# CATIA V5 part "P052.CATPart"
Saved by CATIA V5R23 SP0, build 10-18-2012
Part number: P052
Definition: ISO 4762 Vis Chc M8x45
Publications: "Mating Edge", "Axis"
Bounding box of the stored display mesh (mm): x -45 to 8, y -6.5 to 6.5, z -6.453 to 6.453
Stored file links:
  C:\wamp\www\COURS\CONCEPTION GMP1\TITRE 02-SEMESTRE 2\03-TP7-PRESSE MECANIQUE\eleve\P052.CATPart
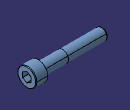
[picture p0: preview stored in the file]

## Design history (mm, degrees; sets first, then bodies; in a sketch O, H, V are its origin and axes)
Parameters
  Material = "St"
  d_dia = 8 mm
  l_nom = 45 mm
  k_head_depth_max = 8 mm
  s_nom = 6 mm
  r_min = 0.4 mm
  ds_max = 8 mm
  e = 6.86 mm
  t_min = 4 mm
  p_pitch = 1.25 mm
  Threading = 28 mm
  dk_max = 13 mm
  PartNumber = "ISO 4762 Vis Chc M8x45"
Body1 "PartBody" (main body)
  Sketch1 on yz-plane, origin (0, 0, 0), H (0, 1, 0), V (0, 0, 1)
    circle A1 centre (0, 0) radius 6.5
    radius A1 = 6.5 {= dk_max /2}
  Pad1: profile Sketch1, direction (1, 0, 0), length 8 {= k_head_depth_max}
  Fillet1: radius 0.4 {= r_min}, on edge [face of Pad1 | face of Pad1]
  Body2
    Sketch2 on face of Pad1, origin (8, 0, 0), H (0, 1, 0), V (0, 0, 1)
      point P1 (3, -1.7321)
      point P2 (3, 1.7321)
      point P3 (0, 3.4641)
      point P4 (-3, 1.7321)
      point P5 (-3, -1.7321)
      point P6 (0, -3.4641)
      point P7 (3, 0)
      line L1 (3, -1.7321) -> (3, 1.7321)
      line L2 (3, 1.7321) -> (0, 3.4641)
      line L3 (0, 3.4641) -> (-3, 1.7321)
      line L4 (-3, 1.7321) -> (-3, -1.7321)
      line L5 (-3, -1.7321) -> (0, -3.4641)
      line L6 (0, -3.4641) -> (3, -1.7321)
      construction line L7 (0, 0) -> (3, 0)
      construction circle A1 centre (0, 0) radius 3.4641
      construction arc A2 centre (-3, -1.7321) radius 3.4641 from (-3, 1.7321) to (0, -3.4641) cw
      construction arc A3 centre (3, 1.7321) radius 3.4641 from (0, 3.4641) to (3, -1.7321) ccw
      point P8 (-3, -1.7321)
      point P9 (3, 1.7321)
      distance L1 L4 = 6 {= s_nom}
      horizontal: L7 H
      coincidence: A1 P1, A1 P2, A1 P3, A1 P4, A1 P5, A1 P6, A2 P4, A2 P6, A2 O, P8 P5, A3 P3, A3 P1, A3 O, P9 P2
      midpoint: P7 L1
    Pad2: profile Sketch2, direction (-1, 0, 0), length 5.9769 {= t_min +(e /3.47)}
    Body3
      Sketch3 on zx-plane, origin (0, 0, 0), H (-1, 0, 0), V (0, 0, 1)
        point P1 (-2.0197, 0)
        line L1 (-2.0197, 0) -> (-4, 3.43)
        line L2 (-4, 3.43) -> (-8, 3.43)
        line L3 (-8, 3.43) -> (-8, 0)
        axis line L4 (-46.2384, 0) -> (26.3409, 0)
        reference projected line E1 (-8, -6.9227) -> (-8, 6.9227) from edge [face of Pad2 | face of Pad2]
        length L2 = 4 {= t_min}
        angle L1 L4 = 60
        distance L2 L4 = 3.43 {= e /2}
        horizontal: L2 H, L4 H
        perpendicularity: L3 L2
        fix: L4
        coincidence: L3 E1, P1 L4
      Shaft1: profile Sketch3, axis Sketch3.L4, angle 360
    Intersect1: tool Body3
  Remove1: tool Body2
  Sketch4 on xy-plane, origin (0, 0, 0), H (1, 0, 0), V (0, 1, 0)
    line L1 (0, 0) -> (0, 4)
    line L2 (0, 4) -> (-17, 4)
    line L3 (-17, 4) -> (-17, 3.9024)
    line L4 (-17, 3.9024) -> (-45, 3.9024)
    line L5 (-45, 3.9024) -> (-45, 0)
    axis line L6 (-192.3446, 0) -> (99.1594, 0)
    distance L5 L1 = 45 {= l_nom}
    distance L3 L5 = 28 {= Threading}
    distance L2 L6 = 4 {= ds_max /2}
    distance L4 L6 = 3.9024 {= d_dia /2.05}
    vertical: L1 V, L3 V, L5 V
    horizontal: L2 H, L4 H, L6 H
    fix: L6
  Shaft2: profile Sketch4, axis Sketch4.L6, angle 360
  Fillet2: radius 0.4 {= r_min}, on edge [face of Shaft2 | face of Pad1]
  Chamfer1: length 1.25 {= p_pitch}, angle 45, on edge [face of Shaft2 | face of Shaft2]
